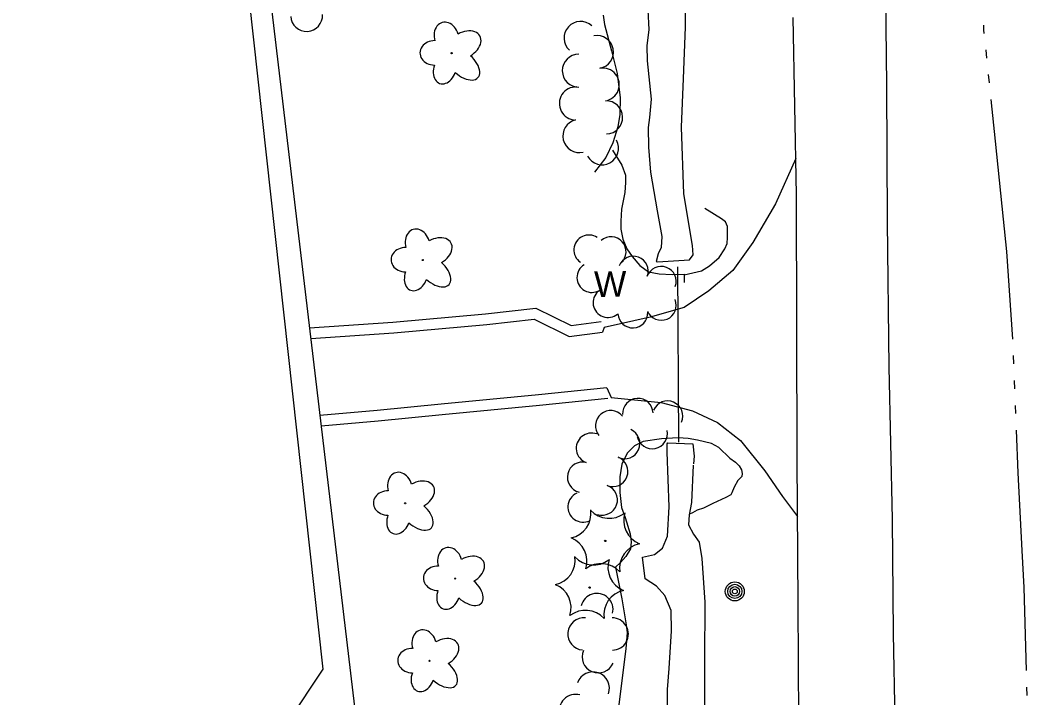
# Model space of a CAD drawing. Extents: x 589250 to 1188077, y 162953 to 363065.
# Drawn here: x 592580.5 to 592816.5, y 174945.5 to 175104.5 of the extents above; entities that cross this region are included whole.
import ezdxf

# ---------------------------------------------------------------- set-up
doc = ezdxf.new("R2010")
doc.units = 0
for name, color, linetype in [('E_BLD', 7, 'Continuous'), ('E_DRN_Pipe', 7, 'Continuous'), ('E_DRN_RipRap', 7, 'Continuous'), ('E_DWY', 7, 'Continuous'), ('E_LAND_TreeLine_P', 7, 'Continuous'), ('E_LAND_Vegetation', 7, 'Continuous'), ('E_MAP_Limits', 7, 'Continuous'), ('E_MISCPROP', 7, 'Continuous'), ('E_RDWY', 7, 'Continuous'), ('E_WAL', 7, 'Continuous'), ('E_WAL_Text', 7, 'Continuous'), ('E_WTR_FlowLine', 7, 'Continuous')]:
    doc.layers.add(name, color=color, linetype=linetype)

msp = doc.modelspace()

# ---------------------------------------------------------------- linework, layer by layer
at = {"layer": 'E_BLD'}
msp.add_line((592638.46, 175115.52), (592669, 174858.96), dxfattribs=at)
at = {"layer": 'E_DRN_Pipe'}
msp.add_line((592734.63, 175046.62), (592734.85, 175005.5), dxfattribs=at)
at = {"layer": 'E_DRN_RipRap'}
for p, q in [((592736.51, 175102.85), (592736.35, 175121.43)), ((592727.7, 175106.88), (592727.88, 175102.34)), ((592727.88, 175102.34), (592727.47, 175098.54)), ((592736.02, 175090.85), (592736.51, 175102.85)), ((592727.47, 175098.54), (592727.5, 175095.02)), ((592727.5, 175095.02), (592728.46, 175085.96)), ((592735.54, 175079.44), (592736.02, 175090.85)), ((592728.46, 175085.96), (592728.06, 175081.72)), ((592728.06, 175081.72), (592727.78, 175079.37)), ((592727.78, 175079.37), (592727.82, 175074.69)), ((592736.11, 175063.79), (592735.54, 175079.44)), ((592727.82, 175074.69), (592728.31, 175068.85)), ((592728.31, 175068.85), (592729.85, 175059.79)), ((592738.11, 175051.67), (592736.11, 175063.79)), ((592729.85, 175059.79), (592730.93, 175053.8)), ((592730.93, 175053.8), (592730.8, 175051.17)), ((592730.8, 175051.17), (592730.08, 175049.7)), ((592738.28, 175049.47), (592738.11, 175051.67)), ((592730.08, 175049.7), (592729.66, 175047.94)), ((592737.41, 175048.3), (592738.28, 175049.47)), ((592729.66, 175047.94), (592729.95, 175047.79)), ((592729.95, 175047.79), (592737.41, 175048.3)), ((592732.22, 175005.09), (592732.36, 175005.38)), ((592732.23, 175003.19), (592732.22, 175005.09)), ((592732.36, 175005.38), (592738.21, 175005.14)), ((592738.21, 175005.14), (592738.53, 175002.22)), ((592732.64, 174990.32), (592732.23, 175003.19)), ((592738.53, 175002.22), (592738.4, 175000.46)), ((592738.26, 175000.15), (592737.89, 174991.37)), ((592732.26, 174983.44), (592732.64, 174990.32)), ((592737.89, 174991.37), (592737.33, 174988.44)), ((592737.33, 174988.44), (592737.21, 174986.1)), ((592737.21, 174986.1), (592738.4, 174983.91)), ((592731.11, 174980.65), (592732.26, 174983.44)), ((592738.4, 174983.91), (592739.73, 174982.02)), ((592729.22, 174979.17), (592731.11, 174980.65)), ((592739.73, 174982.02), (592740.35, 174978.23)), ((592726.45, 174978.56), (592729.22, 174979.17)), ((592727.07, 174973.45), (592726.45, 174978.56)), ((592740.35, 174978.23), (592741.02, 174967.99)), ((592729.72, 174971.71), (592727.07, 174973.45)), ((592731.64, 174969.54), (592729.72, 174971.71)), ((592733.13, 174966.04), (592731.64, 174969.54)), ((592741.02, 174967.99), (592740.99, 174954.39)), ((592733.18, 174961.21), (592733.13, 174966.04)), ((592732.66, 174952.43), (592733.18, 174961.21)), ((592740.99, 174954.39), (592740.97, 174939.17)), ((592732.27, 174947.45), (592732.66, 174952.43)), ((592732.21, 174936.63), (592732.27, 174947.45))]:
    msp.add_line(p, q, dxfattribs=at)
at = {"layer": 'E_DWY'}
for p, q in [((592762.39, 175072.07), (592757.58, 175061.44)), ((592757.58, 175061.44), (592752.26, 175052.33)), ((592752.26, 175052.33), (592747.57, 175045.81)), ((592747.57, 175045.81), (592741.99, 175041.01)), ((592741.99, 175041.01), (592736.2, 175037.07)), ((592736.2, 175037.07), (592728.23, 175034.85)), ((592667.93, 175033.67), (592689.65, 175035.59)), ((592689.65, 175035.59), (592701.44, 175036.93)), ((592701.44, 175036.93), (592709.67, 175032.9)), ((592728.23, 175034.85), (592717.45, 175032.38)), ((592648.37, 175032.31), (592667.93, 175033.67)), ((592668.12, 175031.17), (592689.9, 175033.1)), ((592689.9, 175033.1), (592701, 175034.37)), ((592701, 175034.37), (592709.25, 175030.33)), ((592709.67, 175032.9), (592716.75, 175033.83)), ((592717.45, 175032.38), (592717.07, 175031.35)), ((592648.66, 175029.82), (592668.12, 175031.17)), ((592709.25, 175030.33), (592717.07, 175031.35)), ((592718.07, 175018.23), (592702.06, 175016.6)), ((592718.06, 175018.22), (592719.1, 175015.98)), ((592702.06, 175016.6), (592679.23, 175014.42)), ((592718.32, 175015.74), (592702.31, 175014.11)), ((592719.1, 175015.98), (592730.77, 175014.78)), ((592679.23, 175014.42), (592664.22, 175012.93)), ((592702.31, 175014.11), (592679.47, 175011.93)), ((592730.77, 175014.78), (592738.13, 175012.9)), ((592664.22, 175012.93), (592650.81, 175011.74)), ((592679.47, 175011.93), (592664.45, 175010.44)), ((592738.13, 175012.9), (592743.98, 175010.15)), ((592664.45, 175010.44), (592651.11, 175009.26)), ((592743.98, 175010.15), (592749.42, 175005.87)), ((592749.42, 175005.87), (592755.09, 174998.79)), ((592755.09, 174998.79), (592759.25, 174992.78)), ((592759.25, 174992.78), (592762.76, 174988.06))]:
    msp.add_line(p, q, dxfattribs=at)
at = {"layer": 'E_LAND_TreeLine_P'}
for centre, radius, start, end in [((592647.68, 175105.63), 3.73, 183.2128, 3.2128), ((592711.91, 175100.34), 3.88, 47.7771, 227.7771), ((592715.74, 175097.06), 3.88, 280.4371, 100.4371), ((592711.5, 175092.68), 3.88, 90.4865, 270.4865), ((592717.1, 175089.42), 3.88, 279.4591, 99.4591), ((592710.82, 175084.97), 3.88, 87.4737, 267.4737), ((592717.89, 175081.73), 3.88, 271.7054, 91.7054), ((592711.62, 175077.34), 3.88, 103.5784, 283.5784), ((592716.92, 175074.47), 3.88, 208.7872, 28.7872), ((592713.84, 175050.62), 3.5, 55.662, 235.662), ((592719.06, 175050.19), 3.5, 311.4956, 131.4956), ((592724.26, 175045.64), 3.5, 339.7142, 159.7142), ((592714.56, 175044.14), 3.5, 120.6279, 300.6279), ((592730.82, 175043.23), 3.5, 339.9304, 159.9304), ((592718.32, 175038.25), 3.5, 129.9589, 309.9589), ((592730.82, 175037.61), 3.5, 202.7927, 22.7927), ((592724.16, 175035.82), 3.5, 182.6476, 2.6476), ((592725.33, 175012.22), 3.57, 3.089, 183.089), ((592732.29, 175011.62), 3.57, 336.524, 156.524), ((592718.95, 175009.35), 3.57, 39.7759, 219.7759), ((592714.46, 175004.08), 3.57, 69.6797, 249.6797), ((592722.24, 175005.2), 3.57, 245.6228, 65.6228), ((592728.69, 175007.54), 3.57, 191.2708, 11.2708), ((592719.43, 174998.65), 3.57, 248.6851, 68.6851), ((592712.38, 174997.28), 3.57, 76.916, 256.916), ((592716.98, 174991.95), 3.57, 251.3075, 71.3075), ((592712.51, 174990.3), 3.57, 115.11, 295.11), ((592715.72, 174966.24), 3.79, 346.4502, 166.4502), ((592712.7, 174960.52), 3.79, 84.7759, 264.7759), ((592719.33, 174960.5), 3.79, 270.4865, 90.4865), ((592716.04, 174955.16), 3.79, 156.9342, 336.9342), ((592714.83, 174947.75), 3.85, 340.5034, 160.5034), ((592710.73, 174942.48), 3.85, 74.7778, 254.7778)]:
    msp.add_arc(centre, radius, start, end, dxfattribs=at)
at = {"layer": 'E_LAND_Vegetation'}
for centre, radius in [((592681.68, 175096.78), 0.128), ((592674.9, 175048.25), 0.128), ((592670.78, 174991.16), 0.128), ((592717.69, 174982.35), 0.167), ((592682.5, 174973.51), 0.128), ((592714, 174971.4), 0.167), ((592676.49, 174954.2), 0.128)]:
    msp.add_circle(centre, radius, dxfattribs=at)
for centre, radius, start, end in [((592708.44, 174988.79), 5.9, 282.2939, 8.0588), ((592718.62, 174993.53), 5.9, 222.2893, 308.0542), ((592727.9, 174987.15), 5.9, 162.2939, 248.0588), ((592707.49, 174977.56), 5.9, 342.2939, 68.0588), ((592726.95, 174975.91), 5.9, 102.2939, 188.0588), ((592704.74, 174977.84), 5.9, 282.2939, 8.0588), ((592714.92, 174982.58), 5.9, 222.2893, 308.0542), ((592724.2, 174976.2), 5.9, 162.2939, 248.0588), ((592716.74, 174971.11), 5.91, 42.3337, 128.0098), ((592703.79, 174966.6), 5.9, 342.2939, 68.0588), ((592723.25, 174964.96), 5.9, 102.2939, 188.0588), ((592713.05, 174960.15), 5.91, 42.3337, 128.0098)]:
    msp.add_arc(centre, radius, start, end, dxfattribs=at)
for centre, major_axis, ratio in [((592680.46, 175100.49), (0.99, -3.48), 0.782863), ((592684.63, 175098.73), (-3.67, -2.09), 0.691916), ((592677.7, 175096.85), (3.45, -0.05), 0.832022), ((592684.31, 175094.21), (-3.54, 3.17), 0.560249), ((592680.1, 175093.1), (1.23, 3.41), 0.716896), ((592673.68, 175051.96), (0.99, -3.48), 0.782863), ((592677.85, 175050.19), (-3.67, -2.09), 0.691916), ((592670.92, 175048.32), (3.45, -0.05), 0.832022), ((592677.53, 175045.68), (-3.54, 3.17), 0.560249), ((592673.32, 175044.56), (1.23, 3.41), 0.716896), ((592669.56, 174994.87), (0.99, -3.48), 0.782863), ((592673.73, 174993.1), (-3.67, -2.09), 0.691916), ((592666.79, 174991.22), (3.45, -0.05), 0.832022), ((592673.41, 174988.59), (-3.54, 3.17), 0.560249), ((592669.2, 174987.47), (1.23, 3.41), 0.716896), ((592681.29, 174977.22), (0.99, -3.48), 0.782863), ((592685.45, 174975.46), (-3.67, -2.09), 0.691916), ((592678.52, 174973.58), (3.45, -0.05), 0.832022), ((592685.14, 174970.94), (-3.54, 3.17), 0.560249), ((592680.92, 174969.83), (1.23, 3.41), 0.716896), ((592675.27, 174957.91), (0.99, -3.48), 0.782863), ((592679.44, 174956.14), (-3.67, -2.09), 0.691916), ((592672.5, 174954.26), (3.45, -0.05), 0.832022), ((592679.12, 174951.63), (-3.54, 3.17), 0.560249), ((592674.91, 174950.51), (1.23, 3.41), 0.716896)]:
    msp.add_ellipse(centre, major_axis=major_axis, ratio=ratio, start_param=1.570796, end_param=4.712389, dxfattribs=at)
at = {"layer": 'E_MAP_Limits'}
for p, q in [((592605.79, 175367.2), (592651.48, 174952.24)), ((592651.48, 174952.24), (592580.53, 174845.29))]:
    msp.add_line(p, q, dxfattribs=at)
at = {"layer": 'E_MISCPROP'}
for radius in [2.23, 1.67, 1.12, 0.558]:
    msp.add_circle((592748.06, 174970.49), radius, dxfattribs=at)
at = {"layer": 'E_RDWY'}
for p, q in [((592783.7, 175089.24), (592783.24, 175126.21)), ((592762.55, 175063.53), (592761.77, 175105.17)), ((592783.83, 175057.23), (592783.7, 175089.24)), ((592762.65, 175001.35), (592762.55, 175063.53)), ((592784.26, 175023.1), (592783.83, 175057.23)), ((592784.99, 174987.41), (592784.26, 175023.1)), ((592762.93, 174967.64), (592762.65, 175001.35)), ((592785.22, 174960.64), (592784.99, 174987.41)), ((592763.13, 174927.84), (592762.93, 174967.64)), ((592785.92, 174928.35), (592785.22, 174960.64))]:
    msp.add_line(p, q, dxfattribs=at)
at = {"layer": 'E_WAL'}
for p, q in [((592717.18, 175105.73), (592717.52, 175103.49)), ((592717.52, 175103.49), (592719.18, 175097.31)), ((592719.18, 175097.31), (592720.5, 175091.98)), ((592720.5, 175091.98), (592721.19, 175086.33)), ((592721.19, 175086.33), (592721.12, 175082.37)), ((592721.12, 175082.37), (592720.61, 175079.48)), ((592720.61, 175079.48), (592719.47, 175075.74)), ((592719.47, 175075.74), (592717.79, 175072.3)), ((592719.37, 175074.03), (592721.54, 175070.52)), ((592717.79, 175072.3), (592715.15, 175068.86)), ((592721.54, 175070.52), (592722.41, 175068.18)), ((592722.41, 175068.18), (592722.43, 175066.47)), ((592722.43, 175066.47), (592722.24, 175064.12)), ((592722.24, 175064.12), (592721.52, 175060.16)), ((592721.52, 175060.16), (592721.33, 175057.39)), ((592744.93, 175057.91), (592741.07, 175060.34)), ((592721.33, 175057.39), (592721.35, 175055.47)), ((592745.9, 175057.17), (592744.93, 175057.91)), ((592746.34, 175056.11), (592745.9, 175057.17)), ((592746.35, 175054.83), (592746.34, 175056.11)), ((592721.35, 175055.47), (592721.79, 175053.12)), ((592746.26, 175052.16), (592746.36, 175053.55)), ((592746.36, 175053.55), (592746.35, 175054.83)), ((592721.79, 175053.12), (592722.77, 175050.89)), ((592745.74, 175050.87), (592746.26, 175052.16)), ((592722.77, 175050.89), (592723.96, 175049.08)), ((592723.96, 175049.08), (592725.8, 175046.96)), ((592742.14, 175046.89), (592744.37, 175048.83)), ((592744.37, 175048.83), (592745.74, 175050.87)), ((592725.8, 175046.96), (592727.84, 175045.48)), ((592740.23, 175045.7), (592742.14, 175046.89)), ((592727.84, 175045.48), (592730.3, 175044.97)), ((592730.3, 175044.97), (592733.4, 175044.89)), ((592733.4, 175044.89), (592736.18, 175044.91)), ((592736.18, 175044.81), (592740.23, 175045.7)), ((592736.18, 175044.91), (592736.19, 175042.99)), ((592730.84, 175006.31), (592726.58, 175005.63)), ((592734.79, 175006.56), (592730.84, 175006.31)), ((592737.15, 175006.36), (592734.79, 175006.56)), ((592739.29, 175005.95), (592737.15, 175006.36)), ((592724.56, 175004.65), (592722.86, 175002.93)), ((592726.58, 175005.63), (592724.56, 175004.65)), ((592742.6, 175005.23), (592739.29, 175005.95)), ((592744.32, 175004.29), (592742.6, 175005.23)), ((592746.9, 175001.75), (592744.32, 175004.29)), ((592722.86, 175002.93), (592721.6, 175000.36)), ((592746.9, 175001.75), (592748.2, 175000.79)), ((592721.6, 175000.36), (592721.09, 174997.36)), ((592748.2, 175000.79), (592749.07, 174999.94)), ((592749.07, 174999.94), (592749.63, 174999.02)), ((592721.09, 174997.36), (592721.12, 174993.73)), ((592749.71, 174997.48), (592748.79, 174996.55)), ((592749.63, 174999.02), (592749.76, 174998.16)), ((592749.76, 174998.16), (592749.71, 174997.48)), ((592747.88, 174994.94), (592747.4, 174993.59)), ((592748.79, 174996.55), (592747.88, 174994.94)), ((592721.12, 174993.73), (592721.47, 174990.21)), ((592745.99, 174992.53), (592742.93, 174991.09)), ((592747.1, 174993.15), (592745.99, 174992.53)), ((592747.4, 174993.59), (592747.1, 174993.15)), ((592721.47, 174990.21), (592722.35, 174987.87)), ((592740.72, 174990.02), (592739.25, 174989.52)), ((592742.93, 174991.09), (592740.72, 174990.02)), ((592722.35, 174987.87), (592723.56, 174984.03)), ((592738.15, 174988.95), (592737.41, 174988.58)), ((592739.25, 174989.52), (592738.15, 174988.95)), ((592723.56, 174984.03), (592723.79, 174982.11)), ((592723.59, 174980.51), (592722.53, 174978.68)), ((592723.79, 174982.11), (592723.59, 174980.51)), ((592722.53, 174978.68), (592721.27, 174977.28)), ((592721.27, 174977.28), (592720.1, 174976.2)), ((592720.1, 174976.2), (592721.55, 174968.74)), ((592721.55, 174968.74), (592722.57, 174962.66)), ((592722.57, 174962.66), (592722.8, 174960.74)), ((592722.8, 174960.74), (592722.51, 174957.1)), ((592722.51, 174957.1), (592720.51, 174940.74))]:
    msp.add_line(p, q, dxfattribs=at)
at = {"layer": 'E_WTR_FlowLine'}
for p, q in [((592806.33, 175103.37), (592806.38, 175102.28)), ((592806.38, 175102.28), (592806.47, 175101.42)), ((592806.87, 175097.55), (592807.07, 175095.61)), ((592807.47, 175091.74), (592807.67, 175089.8)), ((592808.07, 175085.93), (592809.09, 175076.12)), ((592809.09, 175076.12), (592810.97, 175057.85)), ((592810.97, 175057.85), (592811.76, 175050.21)), ((592811.76, 175050.21), (592813.12, 175029.71)), ((592813.33, 175025.82), (592813.41, 175023.88)), ((592813.56, 175019.98), (592813.64, 175018.04)), ((592813.79, 175014.15), (592813.86, 175012.2)), ((592814.01, 175008.31), (592814.4, 174998.3)), ((592814.4, 174998.3), (592815.34, 174980.11)), ((592815.34, 174980.11), (592815.8, 174971.4)), ((592815.8, 174971.4), (592816.35, 174951.9)), ((592816.47, 174948.01), (592816.52, 174946.06))]:
    msp.add_line(p, q, dxfattribs=at)

# ---------------------------------------------------------------- texts
at = {"layer": 'E_WAL_Text'}
msp.add_text('W', height=6, rotation=0.4865, dxfattribs=at).set_placement((592715.09, 175039.58))

doc.saveas('drawing.dxf')
